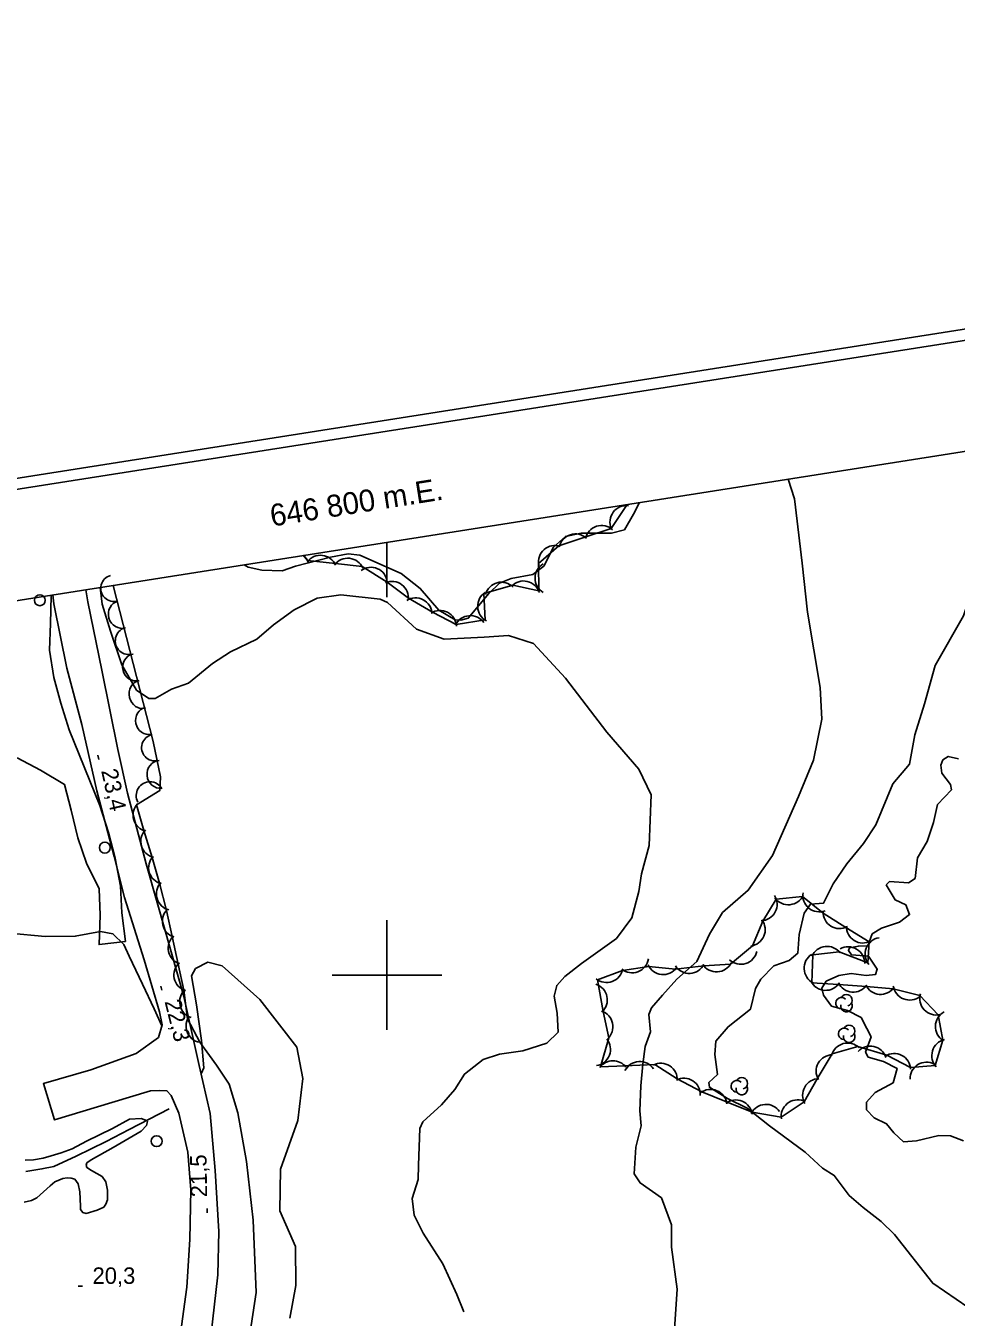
# Model space of a CAD drawing. Extents: x 646142 to 649934, y 5874075 to 5876351.
# Drawn here: x 646734.2 to 646903.8, y 5875737.6 to 5875973 of the extents above; entities that cross this region are included whole.
import ezdxf

# ---------------------------------------------------------------- set-up
doc = ezdxf.new("R2010")
doc.units = 0
for name, color, linetype in [('Niveau 1', 7, 'Continuous'), ('Niveau 2', 7, 'Continuous'), ('Niveau 21', 7, 'Continuous'), ('Niveau 3', 7, 'Continuous'), ('Niveau 36', 7, 'Continuous'), ('Niveau 4', 7, 'Continuous'), ('Niveau 44', 7, 'Continuous'), ('Niveau 60', 7, 'Continuous'), ('Niveau 61', 7, 'Continuous')]:
    doc.layers.add(name, color=color, linetype=linetype)

msp = doc.modelspace()

# ---------------------------------------------------------------- linework, layer by layer
at = {"layer": 'Niveau 1'}
for points in [[(646891.02, 5875816.46), (646891.64, 5875817.05), (646895.12, 5875816.82), (646896.3, 5875817.59), (646896.75, 5875821.35), (646898.5, 5875824.33), (646899.67, 5875827.82), (646900.41, 5875831.09), (646902.94, 5875833.76), (646902.77, 5875834.72), (646901.17, 5875836.79), (646901.01, 5875838.22), (646901.37, 5875839.19), (646902.34, 5875839.82), (646904.22, 5875839.4)], [(646905.1, 5875769.78), (646902.76, 5875770.72), (646900.63, 5875770.76), (646896.55, 5875769.76), (646894.21, 5875769.61), (646892.42, 5875771.24), (646891.1, 5875772.88), (646888.85, 5875774), (646887.43, 5875775.45), (646887.45, 5875776.84), (646889.04, 5875778.59), (646892.29, 5875780.36), (646893.04, 5875782.99), (646890.55, 5875784.26), (646887.76, 5875785.03), (646887.26, 5875785.95), (646888.28, 5875788.73), (646887.48, 5875790.25), (646886.46, 5875792.27), (646883.97, 5875793.54), (646881.07, 5875794.3), (646879.58, 5875796.32), (646879.27, 5875797.62), (646880.11, 5875798.87), (646882.41, 5875799.89), (646884.67, 5875800.27), (646887.41, 5875799.9), (646889.06, 5875800.09), (646889.06, 5875800.09), (646889.41, 5875801.06), (646887.83, 5875803.42), (646884.7, 5875803.69), (646884.15, 5875804.49), (646884.33, 5875804.98), (646885.97, 5875805.28), (646887.69, 5875805.31), (646888.48, 5875807.48), (646890.15, 5875808.55), (646893.48, 5875809.63), (646895.29, 5875811), (646894.64, 5875812.77), (646892.64, 5875813.7), (646891.02, 5875816.46)], [(646734.05, 5875766.26), (646735.58, 5875766.35), (646737.32, 5875766.64), (646738.77, 5875767.03), (646740.64, 5875767.62), (646742.64, 5875768.35), (646745.23, 5875769.71), (646749.95, 5875772), (646753.05, 5875773.71), (646755.22, 5875773.88), (646756.2, 5875773.49), (646756.33, 5875773.28), (646756.2, 5875772.6), (646755.18, 5875771.54), (646750.12, 5875768.56), (646746.08, 5875766.35), (646745.27, 5875765.75), (646745.15, 5875765.33), (646745.32, 5875764.95), (646746.13, 5875764.39), (646748.08, 5875763.29), (646748.76, 5875762.31), (646749.06, 5875760.78), (646749.06, 5875759.04), (646748.76, 5875758.27), (646748.38, 5875757.72), (646747.19, 5875757.12), (646745.19, 5875756.57), (646744.55, 5875756.7), (646744.17, 5875757.25), (646744.13, 5875757.89), (646744, 5875760.48), (646743.7, 5875761.97), (646743.11, 5875762.78), (646742.43, 5875762.95), (646741.7, 5875763.03), (646740.94, 5875762.9), (646739.49, 5875762.31), (646738.6, 5875761.59), (646736.18, 5875759.42), (646735.24, 5875758.91), (646733.88, 5875758.61)]]:
    msp.add_lwpolyline(points, dxfattribs=at)
at = {"layer": 'Niveau 2'}
for points in [[(646917.91, 5875897.39), (646917.28, 5875895.43), (646914.11, 5875886.36), (646909.27, 5875877.84), (646905.14, 5875865.47), (646899.96, 5875856.4)], [(646873.15, 5875890.35), (646874.33, 5875886.75), (646875.72, 5875875.05), (646876.7, 5875866.09), (646878.99, 5875852.41), (646879.27, 5875846.63), (646877.78, 5875839.14)], [(646774.01, 5875874.75), (646774.72, 5875874.32), (646777.2, 5875873.79), (646780.92, 5875873.64), (646783.32, 5875874.5), (646789.73, 5875876.12), (646792.96, 5875876.72), (646795.07, 5875876.5), (646802.61, 5875873.19), (646806.09, 5875870.45), (646809.47, 5875866.48), (646812.44, 5875864.73), (646813.48, 5875864.68), (646814.84, 5875865.01), (646818.56, 5875869.51), (646820.55, 5875871.43), (646822.65, 5875872.26), (646826.62, 5875873.01), (646828.59, 5875874.52), (646830.35, 5875877.98), (646832.56, 5875879.92), (646835.45, 5875880.49), (646840.94, 5875880.49), (646843.3, 5875881.11), (646844.95, 5875883.98), (646846.08, 5875886.09)], [(646779.3, 5875863.81), (646776.29, 5875861.18), (646771.5, 5875858.88), (646768.2, 5875856.75), (646763.85, 5875853.15), (646760.72, 5875852.09), (646757.78, 5875850.41), (646756.62, 5875850.39), (646754.36, 5875851.93), (646751.65, 5875856.51), (646749.59, 5875862.63), (646748.11, 5875867.59), (646747.72, 5875870.62)], [(646847.79, 5875823.62), (646848.17, 5875832.86), (646845.93, 5875837.49), (646840.09, 5875844.26), (646832.54, 5875854.09), (646826.75, 5875860.41), (646822.2, 5875861.86), (646817.71, 5875861.57), (646810.46, 5875861.19), (646805.39, 5875863.05), (646800.11, 5875867.91), (646798.78, 5875868.46), (646791.62, 5875869.26), (646787.29, 5875868.64), (646783.12, 5875866.52), (646779.3, 5875863.81)], [(646899.96, 5875856.4), (646898, 5875849.44), (646896.26, 5875843.79), (646895.29, 5875838.4), (646892.27, 5875834.86), (646889.17, 5875827.37), (646886.89, 5875823.97), (646883.84, 5875820.26), (646881.36, 5875816.6), (646879.61, 5875813.1), (646877.21, 5875812.88), (646876.06, 5875811.29), (646875.16, 5875807.36), (646874.9, 5875803.97), (646873.32, 5875802.63), (646870.54, 5875801.67), (646868.16, 5875799.25), (646867.19, 5875797.57), (646866.28, 5875793.76), (646862.2, 5875790.56), (646859.95, 5875787.92), (646859.81, 5875785.53), (646860.26, 5875781.88), (646858.7, 5875780.42), (646858.79, 5875779.56), (646859.65, 5875779.03), (646862.12, 5875777.52), (646865.66, 5875775.74), (646869.75, 5875772.51), (646876.26, 5875767.72), (646879.45, 5875764.79), (646881.55, 5875763.48), (646884.31, 5875759.81), (646886.85, 5875757.62)], [(646877.78, 5875839.14), (646875.04, 5875832.55), (646870.32, 5875821.78), (646865.88, 5875815.46), (646861.19, 5875811.37), (646858.79, 5875807.43), (646856.51, 5875802.47), (646852.87, 5875799.26), (646850.25, 5875796.34), (646848.25, 5875794.02), (646847.75, 5875792.8), (646848.04, 5875789.64), (646847.06, 5875786.97), (646846.67, 5875783.74), (646846.29, 5875779.81), (646846.09, 5875775.26), (646846.34, 5875772.51), (646845.38, 5875768.62), (646845.1, 5875763.78), (646846.15, 5875762.11), (646850.08, 5875759.38), (646851.88, 5875754.49), (646851.87, 5875750.43), (646852.94, 5875742.74), (646852.41, 5875735.44)], [(646814.05, 5875738.62), (646812.77, 5875741.78), (646810.2, 5875747.34), (646806.63, 5875752.96), (646804.99, 5875756.26), (646804.6, 5875759.29), (646805.73, 5875762.73), (646805.78, 5875765.35), (646805.98, 5875772), (646806.54, 5875773.23), (646809.95, 5875776.36), (646812.42, 5875779.14), (646814.13, 5875781.96), (646817.54, 5875784.63), (646820.51, 5875785.55), (646824.77, 5875786.17), (646829.18, 5875787.61), (646831.22, 5875789.6), (646831.07, 5875793.07), (646830.5, 5875796.14), (646830.98, 5875798.11), (646832.42, 5875799.73), (646835.46, 5875802.12), (646841.84, 5875806.65), (646844.67, 5875810.41), (646845.93, 5875815.21), (646846.45, 5875818.41), (646847.79, 5875823.62)], [(646731.18, 5875807.65), (646737.69, 5875807.01), (646743.2, 5875807.07), (646747.81, 5875807.9), (646750.06, 5875807.52), (646752.06, 5875805.53), (646752.99, 5875803.43), (646755.42, 5875798.31), (646757.59, 5875793.84), (646758.98, 5875790.71)], [(646766.12, 5875782.01), (646766.62, 5875783.07), (646766.18, 5875788.09), (646765.29, 5875794.56), (646764.35, 5875799.87), (646765.08, 5875801.18), (646767.33, 5875802.32), (646769.95, 5875801.69), (646776.84, 5875795.51), (646783.59, 5875786.86), (646784.68, 5875781.16), (646783.79, 5875773.49), (646780.6, 5875764.62), (646780.51, 5875757.04), (646783.32, 5875750.5), (646783.41, 5875743.42), (646782.33, 5875737.48)], [(646886.85, 5875757.62), (646890.11, 5875755.11), (646892.56, 5875752.74), (646899.51, 5875743.84), (646908.07, 5875738.03), (646920.82, 5875730.75), (646931.39, 5875726.44), (646938.42, 5875719.88), (646944.55, 5875713.62), (646951.93, 5875709.06), (646960.34, 5875707.75), (646971.9, 5875701.61), (646985.99, 5875697.51), (647000.79, 5875695.33), (647024.14, 5875697.86), (647040.52, 5875701.17), (647059.42, 5875702.25), (647079.92, 5875698.91), (647104.84, 5875688.27), (647120.69, 5875669.66)]]:
    msp.add_lwpolyline(points, dxfattribs=at)
at = {"layer": 'Niveau 21'}
for points in [[(646763.66, 5875713.19), (646765.49, 5875719.06), (646766.27, 5875724.62), (646767.88, 5875734.13), (646769.19, 5875745.34), (646769.36, 5875753.28), (646768.71, 5875764.38), (646767.79, 5875774.75), (646765.78, 5875783.49), (646762.99, 5875796.1), (646758.24, 5875812.79), (646756.14, 5875820.24), (646752.74, 5875833.14), (646750.93, 5875841.09), (646748.05, 5875855.56), (646745.51, 5875867.98), (646745.13, 5875870.21)], [(646739.1, 5875869.26), (646739.28, 5875867.66), (646741.63, 5875855.92), (646744.39, 5875845.63), (646747.12, 5875833.58), (646750.31, 5875821.6), (646752.18, 5875814.12), (646755.76, 5875802.77), (646758.55, 5875793.3), (646759.04, 5875790.92), (646758.37, 5875788.62), (646754.29, 5875785.7), (646746.03, 5875782.75), (646737.37, 5875780.23), (646739.39, 5875773.58), (646749.83, 5875776.79), (646756.9, 5875778.89), (646758.63, 5875778.98), (646759.91, 5875778.9), (646760.7, 5875778.06), (646762.1, 5875774.84), (646763.71, 5875767.69), (646764.23, 5875760.88), (646764.08, 5875751.78), (646763.53, 5875743.1), (646761.98, 5875731.98)]]:
    msp.add_lwpolyline(points, dxfattribs=at)
at = {"layer": 'Niveau 3'}
for p, q in [((646747.29, 5875840.05), (646747.47, 5875839.27)), ((646758.8, 5875797.98), (646758.99, 5875797.21)), ((646767.25, 5875756.64), (646767.24, 5875757.44)), ((646743.69, 5875743.3), (646744.49, 5875743.3))]:
    msp.add_line(p, q, dxfattribs=at)
at = {"layer": 'Niveau 36'}
for centre in [(646736.73, 5875868.29), (646748.58, 5875823.21), (646758.02, 5875769.72)]:
    msp.add_circle(centre, 1, dxfattribs=at)
at = {"layer": 'Niveau 4'}
msp.add_lwpolyline([(646760.32, 5875775.6), (646753.01, 5875771.84), (646748.82, 5875769.67), (646743.36, 5875766.99), (646739.26, 5875765.12), (646737.11, 5875764.65), (646734.16, 5875764.2)], dxfattribs=at)
at = {"layer": 'Niveau 44'}
for points in [[(646843.71, 5875885.53), (646840.91, 5875881.34), (646836.29, 5875879.85), (646831.32, 5875878.19), (646827.66, 5875875), (646827.69, 5875869.98), (646822.96, 5875871.06), (646817.69, 5875869.55), (646817.89, 5875864.7), (646812.64, 5875863.89), (646808.33, 5875866.11), (646803.93, 5875868.67), (646800.05, 5875871.58), (646795.48, 5875874.44), (646790.65, 5875874.96), (646785.54, 5875875.52), (646784.79, 5875876.45)], [(646750.09, 5875870.99), (646757.4, 5875842.58), (646758.71, 5875836.13), (646758.59, 5875833.6), (646754.34, 5875830.98), (646755.72, 5875826.33), (646757.18, 5875821.39), (646758.55, 5875816.74), (646759.84, 5875811.78), (646760.86, 5875807.03), (646761.94, 5875802), (646762.97, 5875797.26), (646763.68, 5875792.02), (646765.92, 5875787.79)], [(646732.57, 5875839.56), (646736.88, 5875837.32), (646741.21, 5875834.72), (646742.47, 5875830.03), (646743.68, 5875825.01), (646745.23, 5875820.41), (646747.52, 5875815.73), (646747.7, 5875810.88), (646747.52, 5875805.55), (646752.34, 5875806.11), (646751.67, 5875811.35), (646751.42, 5875816.19), (646750.49, 5875821.29), (646749.26, 5875825.98), (646747.69, 5875830.9), (646745.86, 5875835.4), (646743.93, 5875840.17), (646742.1, 5875844.67), (646740.54, 5875849.53), (646739.3, 5875854.22), (646738.51, 5875859.22), (646738.65, 5875864.08), (646738.79, 5875869.07), (646738.78, 5875869.21)], [(646895.46, 5875783.13), (646891.15, 5875785.38), (646885.85, 5875786.95), (646881.18, 5875785.64), (646878.45, 5875781.09), (646876.07, 5875776.86), (646871.89, 5875774.09), (646866.57, 5875775.02), (646861.92, 5875776.86), (646857.43, 5875778.71), (646852.94, 5875781.08), (646848.87, 5875783.72), (646843.38, 5875783.47), (646838.92, 5875783.27), (646840.44, 5875788.57), (646839.44, 5875793.32), (646838.4, 5875799.12), (646842.94, 5875800.84), (646847.77, 5875801.57), (646852.6, 5875801.07), (646857.78, 5875801.67), (646862.63, 5875801.95), (646866.64, 5875805.32), (646868.54, 5875809.79), (646870.95, 5875813.81), (646875.78, 5875814.28), (646879.55, 5875811.25), (646883.67, 5875808.68), (646887.92, 5875806.04), (646887.7, 5875802.19), (646882.47, 5875804.25), (646877.65, 5875803.68), (646877.48, 5875798.58), (646882.32, 5875798.29), (646887.45, 5875797.9), (646892.28, 5875797.5), (646897.19, 5875796.27), (646900.51, 5875792.73), (646901.35, 5875788.14), (646899.96, 5875783.48), (646895.46, 5875783.13)], [(646749.23, 5875617.47), (646754.68, 5875639.27), (646759.47, 5875659.72), (646767.62, 5875694.24), (646771.74, 5875712.84), (646776.2, 5875742.14), (646775.6, 5875755.35), (646774.42, 5875766.04), (646772.82, 5875774.88), (646771.22, 5875780.1), (646768.95, 5875783.55), (646765.92, 5875787.79)]]:
    msp.add_lwpolyline(points, dxfattribs=at)
for centre, radius, start, end in [((646843.66, 5875882.53), 3, 82.9788, 202.9568), ((646839.14, 5875878.92), 3, 47.8497, 167.8277), ((646834.38, 5875877.38), 3, 47.8497, 167.8277), ((646830.64, 5875875.27), 3, 71.064, 191.042), ((646782.94, 5875874.03), 3, 23.8164, 53.3972), ((646787.91, 5875873.49), 3, 23.8164, 143.7943), ((646792.88, 5875872.95), 3, 23.8164, 143.7943), ((646830.01, 5875872.32), 3, 119.8303, 239.8082), ((646797.09, 5875871.29), 3, 6.6734, 126.6514), ((646800.93, 5875868.72), 3, 353.1279, 113.1059), ((646820.88, 5875868.58), 3, 44.9508, 164.9287), ((646824.93, 5875868.8), 3, 17.2112, 137.1891), ((646805.23, 5875865.73), 3, 2.6969, 122.6749), ((646819.55, 5875867.19), 3, 122.361, 242.3389), ((646809.67, 5875863.43), 3, 2.6969, 122.6749), ((646815.23, 5875862.49), 3, 35.0491, 155.027), ((646756.72, 5875829.15), 3, 136.5105, 256.4884), ((646758.14, 5875824.36), 3, 136.5105, 256.4884), ((646759.56, 5875819.56), 3, 136.5105, 256.4884), ((646760.97, 5875814.77), 3, 136.5105, 256.4884), ((646868.14, 5875812.88), 3, 272.4002, 32.3781), ((646873.19, 5875815.8), 3, 215.5718, 335.5498), ((646878.83, 5875814.51), 3, 170.6286, 290.6065), ((646762.07, 5875809.78), 3, 132.1711, 252.1491), ((646882.54, 5875811.46), 3, 178.1509, 298.1289), ((646865.97, 5875808.25), 3, 276.9643, 36.9423), ((646886.78, 5875808.82), 3, 178.1509, 298.1289), ((646763.13, 5875804.89), 3, 132.1711, 252.1491), ((646890.21, 5875803.83), 3, 99.1525, 219.1305), ((646864.52, 5875804.95), 3, 227.5599, 347.5378), ((646880.26, 5875802.22), 3, 36.6855, 156.6634), ((646884.11, 5875802.14), 3, 359.3189, 119.2969), ((646764.18, 5875800), 3, 132.1711, 252.1491), ((646844.72, 5875803.4), 3, 230.7602, 350.7381), ((646850.36, 5875803.08), 3, 204.086, 324.064), ((646855.11, 5875803.29), 3, 213.3029, 333.2809), ((646860.1, 5875803.57), 3, 213.3029, 333.2809), ((646879.07, 5875801.24), 3, 122.7336, 242.7116), ((646840.04, 5875801.63), 3, 230.7602, 350.7381), ((646765.23, 5875795.11), 3, 132.1711, 252.1491), ((646837.19, 5875795.47), 3, 311.8658, 71.8438), ((646880, 5875800.2), 3, 206.615, 326.5929), ((646885.03, 5875799.87), 3, 205.3054, 325.2834), ((646890.01, 5875799.46), 3, 205.3054, 325.2834), ((646895.29, 5875798.43), 3, 188.8198, 308.7978), ((646882.89, 5875794.86), 1.05, 44.1154, 269.804), ((646883.79, 5875794.34), 1.05, 166.9369, 29.6212), ((646883.79, 5875795.39), 1.05, 282.2692, 149.7263), ((646900.14, 5875795.71), 3, 163.1124, 283.0903), ((646766.38, 5875790.69), 3, 147.8803, 267.8583), ((646838.21, 5875790.58), 3, 311.8658, 71.8438), ((646902.99, 5875790.61), 3, 117.9356, 237.9136), ((646883.38, 5875789.28), 1.05, 44.1154, 269.804), ((646884.28, 5875789.81), 1.05, 282.2692, 149.7263), ((646837.77, 5875786.45), 3, 278.8301, 38.808), ((646883.99, 5875784.6), 3, 45.6059, 165.5838), ((646884.28, 5875788.76), 1.05, 166.9369, 29.6212), ((646902.35, 5875785.31), 3, 103.4536, 223.4316), ((646881.25, 5875782.47), 3, 90.7147, 210.6926), ((646888.12, 5875784.05), 3, 17.2703, 137.2482), ((646892.49, 5875782.69), 3, 2.4204, 122.3984), ((646841.24, 5875781.36), 3, 38.5697, 142.8443), ((646846.09, 5875781.24), 3, 33.439, 153.417), ((646849.95, 5875780.92), 3, 357.1076, 117.0856), ((646898.38, 5875781.12), 3, 61.832, 181.8099), ((646854.15, 5875778.2), 3, 357.1076, 117.0856), ((646863.81, 5875779.73), 1.05, 44.1154, 269.804), ((646864.71, 5875780.26), 1.05, 282.2692, 149.7263), ((646878.8, 5875778.11), 3, 90.7147, 210.6926), ((646859, 5875776.15), 3, 7.5302, 127.5082), ((646864.71, 5875779.21), 1.05, 166.9369, 29.6212), ((646863.62, 5875774.24), 3, 7.5302, 127.5082), ((646869.12, 5875773.43), 3, 34.0444, 154.0223), ((646874.89, 5875774.25), 3, 69.0304, 189.0083)]:
    msp.add_arc(centre, radius, start, end, dxfattribs=at)
for centre, major_axis, ratio, start_param, end_param in [((646750.27, 5875870.47), (-2.34, -0.65), 0.997449, 4.712389, 7.853982), ((646751.66, 5875865.7), (0.69, -2.45), 0.952628, 3.141593, 6.283185), ((646752.99, 5875860.88), (-2.39, -0.75), 0.99999, 4.712389, 7.853982), ((646754.23, 5875856.07), (0.57, -2.41), 0.970147, 3.141593, 6.283185), ((646755.41, 5875851.14), (0.6, -2.53), 0.925819, 3.141593, 6.283185), ((646756.5, 5875846.31), (0.51, -2.45), 0.919919, 3.141593, 6.283185), ((646757.7, 5875841.43), (-2.37, -0.52), 0.997449, 4.712389, 7.853982), ((646758.7, 5875836.56), (0.24, -2.54), 0.952628, 3.141593, 6.283185), ((646756.8, 5875832.71), (-1.21, 2.19), 0.99999, 4.712389, 7.853982)]:
    msp.add_ellipse(centre, major_axis=major_axis, ratio=ratio, start_param=start_param, end_param=end_param, dxfattribs=at)
at = {"layer": 'Niveau 60'}
msp.add_line((646800, 5875878.84), (646800, 5875868.84), dxfattribs=at)
for points in [[(646142.26, 5875797.64), (649662.59, 5876351.49), (649933.58, 5874629.01), (646413.32, 5874074.83), (646142.26, 5875797.64)], [(646144.55, 5875795.97), (649660.92, 5876349.21), (649931.28, 5874630.65), (646414.98, 5874077.12), (646144.55, 5875795.97)]]:
    msp.add_lwpolyline(points, dxfattribs=at)
msp.add_lwpolyline([(646167.42, 5875779.32), (649130.97, 5876245.57), (649395.18, 5874566.24), (646431.63, 5874099.99)], close=True, dxfattribs=at)
msp.add_lwpolyline([(646167.42, 5875779.32), (649130.97, 5876245.57), (649395.18, 5874566.24), (646431.63, 5874099.99)], close=True, dxfattribs=at)
at = {"layer": 'Niveau 61'}
for points in [[(646800, 5875810), (646800, 5875800), (646800, 5875790)], [(646790, 5875800), (646800, 5875800), (646810, 5875800)]]:
    msp.add_lwpolyline(points, dxfattribs=at)

# ---------------------------------------------------------------- texts
at = {"layer": 'Niveau 3'}
for s, rotation, p in [('23,4 ', 282.8012, (646747.89, 5875837.23)), ('22,3 ', 283.9604, (646759.45, 5875795.18)), ('21,5 ', 90.9709, (646767.24, 5875759.52))]:
    msp.add_text(s, height=3, rotation=rotation, dxfattribs=at).set_placement(p)
msp.add_text('20,3 ', height=3, dxfattribs=at).set_placement((646746.33, 5875743.72))
at = {"layer": 'Niveau 61'}
msp.add_text('646 800 m.E.', height=4, rotation=8.941, dxfattribs=at).set_placement((646779.03, 5875881.71))

doc.saveas('drawing.dxf')
